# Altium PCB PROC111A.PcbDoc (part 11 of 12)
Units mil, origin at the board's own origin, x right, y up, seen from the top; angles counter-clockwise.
Board outline 7700 x 2300 mil, 6 copper layers (Top Layer, GND 1, SIG 1, SIG 2, GND 2, Bottom Layer), stack 61.062 mil thick; 841 components, 632 nets, 2914 pads, 1627 vias.
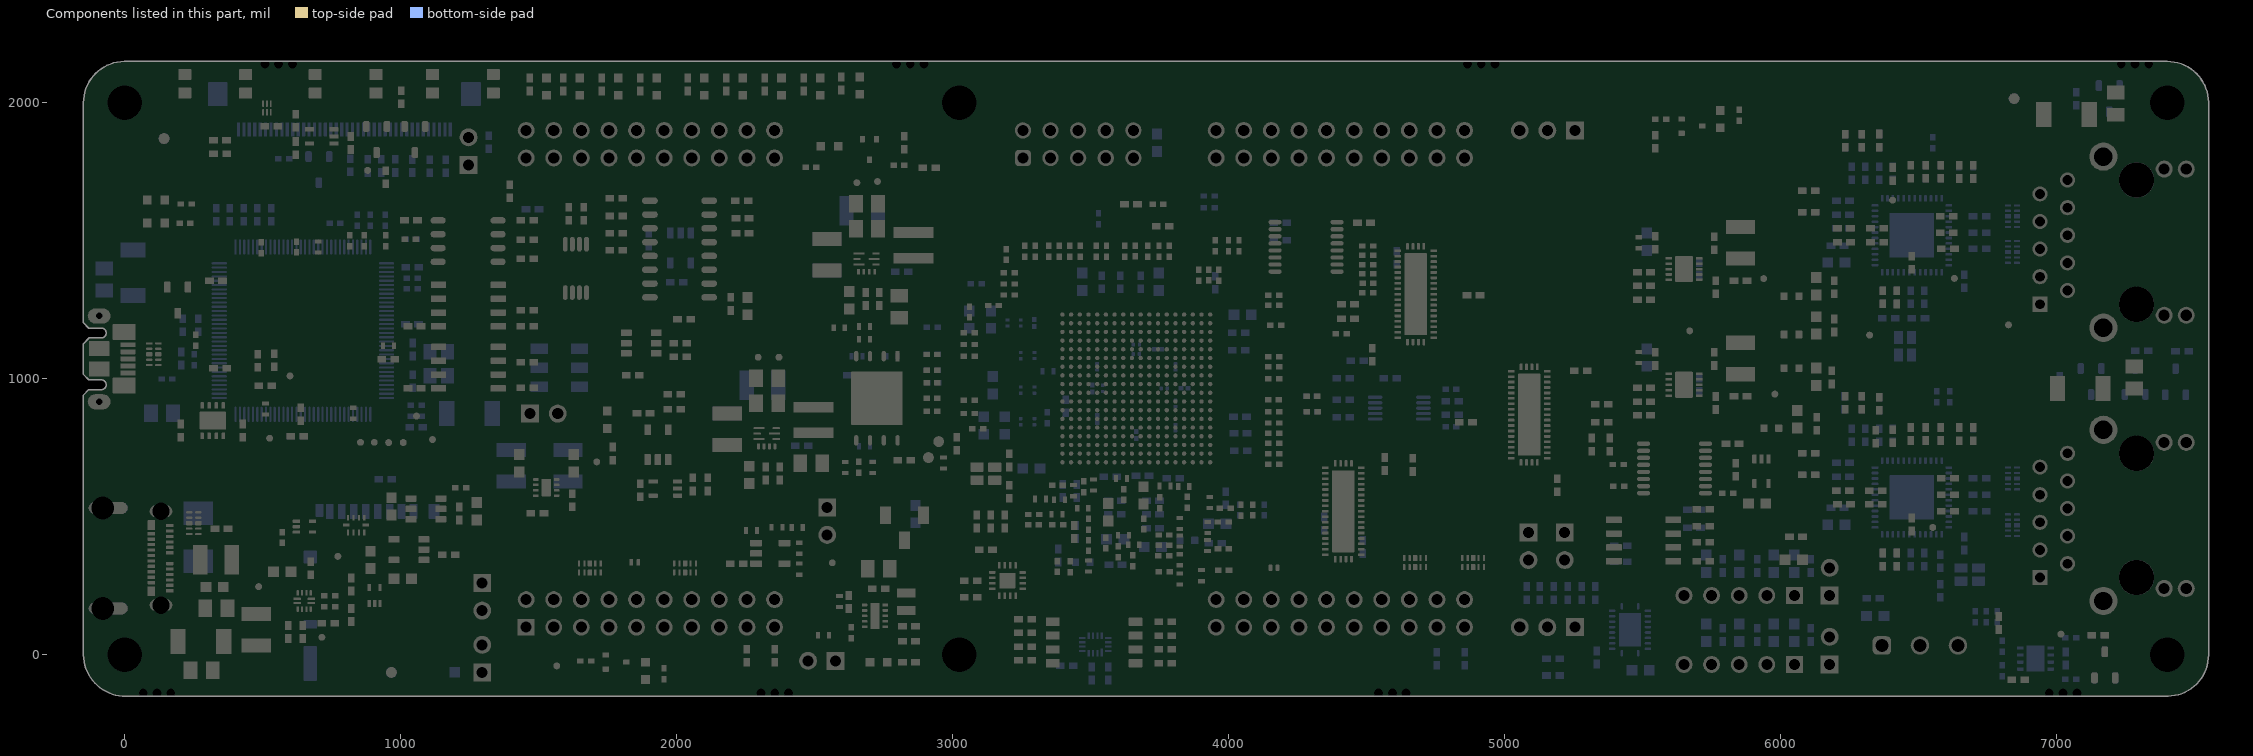
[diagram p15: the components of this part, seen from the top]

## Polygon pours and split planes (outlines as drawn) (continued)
VSYS_5V0_BP_2 on Bottom Layer "NONET_L-01_P-001" (solid, remove dead copper, pour order 310): 3796.91,-55.37 3814.39,-72.85 3902.52,-73.21 3997.16,-73.21 3997.16,230.51 3919.94,230.51 3861.66,172.24 3802.69,172.24 3745.77,115.32 3745.77,-3.83 3796.75,-54.81
VDDA_AM263_3V3 on Bottom Layer "Bottom Layer-VDDA_AM263_3V3" (solid, pour order 140): 18 vertices, not listed, extent 3543.61,365 3915,906.95
SHIELD4 on Bottom Layer "Bottom Layer-SHIELD4" (solid, remove dead copper, pour order 291): -135,818.11 20,818.11 20,1079.72 89.27,1148.99 89.27,1344.48 -135,1344.48
VBUS_XDS_5V0 on Bottom Layer "Bottom Layer-VBUS_USBMICRO_5V0" (solid, pour order 292): 125,1020 134,1020 144.96,1009.04 144.96,926.25 125,906.28 125,813.15 45,813.15 45,1020
GND on Bottom Layer "Bottom Layer-GND 4" (solid, pour order 56): 2446.67,1720 2446.67,1482.62 2641.67,1482.62 2641.67,1720
GND on Bottom Layer "Bottom Layer-GND 10" (solid, pour order 251): 3037.54,1305 3017.54,1285 3017.54,1242.46 3035,1225 3169.11,1225 3188.23,1205.88 3381.63,1205.88 3403.51,1227.76 3403.51,1269.82 3368.33,1305
GND on Bottom Layer "Bottom Layer-GND 12" (solid, pour order 247): 3237.13,839.09 3218.89,820.85 3066.76,820.85 3043.45,797.54 3043.45,724.17 3098.25,669.37 3208.92,669.37 3225.74,652.54 3267.54,652.54 3277.57,662.57 3277.57,738.68 3318.86,779.96 3318.86,830.8 3310.57,839.09
VDDS_AM263_LDO_1V8 on Bottom Layer "Bottom Layer-VDDS_AM263_LDO_1V8" (solid, pour order 289): 31 vertices, not listed, extent 3296.81,601.21 3919.75,1343.61
GND on Bottom Layer "Bottom Layer-GND 7" (solid, pour order 146): 3715,572.41 3715,314.12 3595,314.12 3595,572.41
SHIELD1 on Bottom Layer "NONET_L-01_P-001" (solid, remove dead copper, pour order 283): 26 vertices, not listed, extent -144.23,-103.9 263,582.61
VBUS_TYPEC_5V0 on Bottom Layer "NONET_L-01_P-001" (solid, remove dead copper, pour order 266): 20 vertices, not listed, extent 111.24,142.11 356.09,420
VDDA_AM263_1V8_LDO on Bottom Layer "Bottom Layer-VDDA_AM263_1V8_LDO" (solid, pour order 144): 3578.62,570 3578.62,310 3485,310 3485,376 3510,401 3510,570
GND on Bottom Layer "Bottom Layer-GND 2" (solid, pour order 80): 5415,1509.19 5605,1509.19 5605,1649.19 5415,1649.19
GND on Bottom Layer "Bottom Layer-GND 11" (solid, pour order 229): 26 vertices, not listed, extent 3494.11,920.33 3837.86,1070.93
GND on Bottom Layer "Bottom Layer-GND 1" (solid, pour order 94): 3080,985 3172.46,985 3188.58,968.21 3332.32,968.21 3332.32,1075 3080,1075
VDD_AM263_1V2 on Bottom Layer "Bottom Layer-VDD_AM263_1V2" (solid, pour order 92): 3157.05,965 3173.86,948.19 3315.57,948.19 3315.57,850.24 3225.88,850.24 3215.88,840 3080,840 3080,965
VDD_AM263_1V2 on Bottom Layer "Bottom Layer-VDD_AM263_1V2 1" (solid, pour order 90): 3034.87,1200 3034.87,1090 3315,1090 3315,1200
SHIELD2 on Bottom Layer "Top Layer-SHIELD2" (solid, pour order 192): 7100,179.68 7156.81,122.87 7262.87,122.87 7355,215 7355,266.54 7378.25,289.79 7500,289.79 7500,703.43 7385,703.43 7320,768.43 7320,990 7100,990
SHIELD3 on Bottom Layer "Top Layer-SHIELD3" (solid, pour order 190): 7083.03,1980 7060,1956.97 7060,1813.31 7100,1773.31 7100,1127.87 7115,1112.87 7277.87,1112.87 7355,1190 7355,1256.54 7378.25,1279.79 7500,1279.79 7500,1693.43 7385,1693.43 7320,1758.43 7320,1980
GND on Bottom Layer "Bottom Layer-GND 9" (solid, pour order 180): 6395,1318.62 6395,1246.17 6323.24,1246.17 6323.24,1040.62 6560,1040.62 6560,1286.02 6500,1286.02 6500,1358.25 6395,1358.25 6395,1321.48
VSYS_5V0 on Bottom Layer "Bottom Layer-VSYS_5V0 1" (solid, pour order 82): 5340,1484.19 5340,1358.91 5545,1358.91 5545,1484.19
VDD_AM263_1V2 on Bottom Layer "Bottom Layer-VDD_AM263_1V2 3" (solid, pour order 44): 2340,1100 2340,905 2576.3,905 2576.3,1100
VSYS_3V3 on Bottom Layer "Bottom Layer-VSYS_3V3" (solid, pour order 58): 2701.67,1715 2701.67,1522.62 2966.67,1522.62 2966.67,1715
VSYS_3V3 on Bottom Layer "Bottom Layer-VSYS_3V3 1" (solid, pour order 142): 3950,530 3950,380.76 3865,380.76 3865,530
VSYS_TA_3V3 on Bottom Layer "Bottom Layer-VSYS_TA_3V3" (solid, pour order 134): 380,1935 380,1800 459.37,1800 459.37,1935
GND on Bottom Layer "Bottom Layer-GND 3" (solid, pour order 72): 5415,1090 5605,1090 5605,1230 5415,1230
VSYS_5V0 on Bottom Layer "Bottom Layer-VSYS_5V0 2" (solid, pour order 70): 5335,1065 5335,939.72 5545,939.72 5545,1065
VSYS_5V0 on Bottom Layer "Bottom Layer-VSYS_5V0 3" (solid, pour order 60): 2360,1437.62 2360,1287.62 2616.67,1287.62 2616.67,1422.62 2491.67,1422.62 2476.67,1437.62
GND on Bottom Layer "Bottom Layer-GND 5" (solid, pour order 46): 2085,1096.57 2085,850 2280,850 2280,1096.57
VSYS_5V0 on Bottom Layer "Bottom Layer-VSYS_5V0 4" (solid, pour order 42): 1999.88,805 1999.88,655 2255,655 2255,790 2130,790 2115,805
GND on Bottom Layer "Bottom Layer-GND" (solid, pour order 32): 1310,810 1310,715 1705,715 1705,810
VSYS_5V0 on Bottom Layer "Bottom Layer-VSYS_5V0" (solid, pour order 30): 1550,655 1550,565 1550,501.28 1795.21,501.28 1795.21,690 1675,690 1675,655
VSYS_3V3_BP on SIG 2 "NONET_L-01_P-001" (solid, remove dead copper, pour order 309): 25 vertices, not listed, extent 1241.21,-138.5 3987.3,214.8
VSYS_5V0 on SIG 2 "SIG 1-VSYS_5V0" (solid, remove dead copper, pour order 170): 50 vertices, not listed, extent 1225,-150.47 7080,1510
VSYS_3V3 on SIG 2 "SIG 2-VSYS_3V3" (solid, remove dead copper, pour order 196): 119 vertices, not listed, extent 50.56,-139.06 7515,2090
VDD_XDS3V3 on SIG 2 "SIG 1-VDD_XDS3V3" (solid, remove dead copper, pour order 299): 10,690 10,1680 545,1680 545,1595 1205,1595 1205,755 265,755 265,690
VDD_AM263_1V2 on SIG 2 "SIG 1-VDD_AM263_1V2" (solid, remove dead copper, pour order 168): 28 vertices, not listed, extent 2340,580.04 3900,1184.96
VSD_3V3 on SIG 2 "SIG 2-VSD_3V3" (solid, pour order 284): 859.78,660.43 981.74,660.43 981.74,418.27 569.78,418.27 569.78,601.65 859.78,601.65
SHIELD1 on SIG 2 "NONET_L-01_P-001" (solid, remove dead copper, pour order 279): 26 vertices, not listed, extent -144.23,-103.9 263,582.61
VDD_ETH2_1V1_FILT on SIG 2 "SIG 2-VDD_ETH2_1V1_FILT" (solid, pour order 12): 18 vertices, not listed, extent 6109.18,1283.78 6696.59,1784.26
VDD_ETH1_1V1_FILT on SIG 2 "SIG 2-VDD_ETH1_1V1_FILT" (solid, pour order 84): 17 vertices, not listed, extent 6188.15,539.1 6805,1189.91
SHIELD2 on SIG 2 "Top Layer-SHIELD2" (solid, pour order 211): 7100,179.68 7156.81,122.87 7262.87,122.87 7355,215 7355,266.54 7378.25,289.79 7500,289.79 7500,703.43 7385,703.43 7320,768.43 7320,990 7100,990
SHIELD3 on SIG 2 "Top Layer-SHIELD3" (solid, pour order 209): 7083.03,1980 7060,1956.97 7060,1813.31 7100,1773.31 7100,1127.87 7115,1112.87 7277.87,1112.87 7355,1190 7355,1256.54 7378.25,1279.79 7500,1279.79 7500,1693.43 7385,1693.43 7320,1758.43 7320,1980
VDDS_AM263_LDO_1V8 on SIG 2 "SIG 2-VDDS_AM263_LDO_1V8" (solid, pour order 14): 3994.81,1127.63 3926.04,1127.63 3911.86,1141.81 3843.63,1141.81 3843.63,1103.31 3907.7,1103.31 3941.01,1070 3990.09,1070 4004.85,1084.76 4004.85,1117.72 3993.94,1128.63
VDDS_AM263_LDO_1V8 on SIG 2 "SIG 2-VDDS_AM263_LDO_1V8 1" (solid, pour order 16): 3560,1155.1 3560,1266.01 3563.99,1270 3563.99,1310.97 3555,1319.95 3522.32,1319.95 3507.37,1305 3507.37,1265.8 3480.74,1239.17 3480.74,1165.74 3501.48,1145 3549.9,1145
GND on GND 1 "GND 1-GND" (solid, remove dead copper, pour order 200): 55 vertices, not listed, extent -150,-150 7520,2150.53
SHIELD4 on GND 1 "Bottom Layer-SHIELD4" (solid, pour order 298): 27 vertices, not listed, extent -135,818.11 89.84,1344.61
GND_XDS on GND 1 "SIG 1-VDD_XDS3V3" (solid, pour order 150): 30,1132.67 96.18,1132.67 96.18,1372.54 30,1372.55 -109.74,1372.55 -109.74,1680 545,1680 545,1595 1205,1595 1205,765 265,765 30,765 30,1009.28 30,1035.32
SHIELD1 on GND 1 "NONET_L-01_P-001" (solid, remove dead copper, pour order 275): 26 vertices, not listed, extent -144.23,-103.9 263,582.61
SHIELD3 on GND 1 "Top Layer-SHIELD3" (solid, pour order 235): 7083.03,1980 7060,1956.97 7060,1813.31 7100,1773.31 7100,1127.87 7115,1112.87 7277.87,1112.87 7355,1190 7355,1256.54 7378.25,1279.79 7500,1279.79 7500,1693.43 7385,1693.43 7320,1758.43 7320,1980
SHIELD2 on GND 1 "Top Layer-SHIELD2" (solid, pour order 203): 7100,179.68 7156.81,122.87 7262.87,122.87 7355,215 7355,266.54 7378.25,289.79 7500,289.79 7500,703.43 7385,703.43 7320,768.43 7320,990 7100,990
GND on SIG 1 "NONET_L-01_P-001" (solid, remove dead copper, pour order 316): -15.19,2149.23 7451.59,2149.23 7550,2050.82 7550,-68.99 7468.99,-150 -18.42,-150 -148.4,-20.02 -148.4,2018.56 -18.05,2148.91
VUSB_5V0 on SIG 1 "NONET_L-01_P-001" (solid, remove dead copper, pour order 315): 25 vertices, not listed, extent 2481.98,-150 5432.82,501.78
VSYS_3V3 on SIG 1 "NONET_L-01_P-001" (solid, remove dead copper, pour order 307): 1235.65,-20.36 1239.07,-16.94 1240.24,-16.94 1330.39,-16.94 1344.91,-31.47 2205,-31.47 2411.62,-31.47 2430.37,-50.22 2430.37,-118.32 2411.86,-136.83 1254.42,-136.83 1231.17,-113.58 1231.17,-25.9
VSYS_5V0_BP_1 on SIG 1 "NONET_L-01_P-001" (solid, remove dead copper, pour order 313): 1236.81,202.96 1222.18,188.33 1222.18,95.77 1236.96,80.99 1347.29,80.99 1410.47,144.17 1479.37,144.17 1498.79,163.59 1498.79,229.57 1481.55,246.81 1372.11,246.81 1328.26,202.96
VDDA18_AM263_OSC_PLL on SIG 1 "SIG 1-VDDA18_AM263_OSC_PLL" (solid, remove dead copper, pour order 261): 21 vertices, not listed, extent 3320,426.7 3498.81,784.4
VDDA_AM263_1V8_LDO on SIG 1 "SIG 1-VDDA_AM263_1V8_LDO" (solid, pour order 217): 24 vertices, not listed, extent 3482.52,491.74 3992.51,899.87
SHIELD1 on SIG 1 "NONET_L-01_P-001" (solid, remove dead copper, pour order 277): 20 vertices, not listed, extent -144.23,-103.9 224.84,582.61
VDDS_AM263_LDO_1V8 on SIG 1 "SIG 1-VDDS_AM263_LDO_1V8 3" (solid, pour order 219): 3837.37,1098.64 3845,1091.01 3989.08,1091.01 3995.95,1097.88 3995.95,1114.05 3985,1125 3939.77,1125 3931.83,1117.05 3882.51,1117.05 3860.16,1139.4 3841.97,1139.4 3837.37,1134.8
VDDS_AM263_LDO_1V8 on SIG 1 "SIG 1-VDDS_AM263_LDO_1V8" (solid, pour order 221): 3423.07,758.07 3347,682 3347,630.82 3357.82,620 3426.79,620 3445,638.21 3445,720.25 3459.75,735 3459.75,748.64 3450.33,758.07
VDDS_AM263_LDO_1V8 on SIG 1 "SIG 1-VDDS_AM263_LDO_1V8 1" (solid, pour order 227): 3524.62,1310 3514.99,1300.37 3514.99,1159.77 3531.25,1143.51 3559.82,1143.51 3575,1158.69 3575,1300 3565,1310
SHIELD2 on SIG 1 "Top Layer-SHIELD2" (solid, pour order 207): 7100,179.68 7156.81,122.87 7262.87,122.87 7355,215 7355,266.54 7378.25,289.79 7500,289.79 7500,703.43 7385,703.43 7320,768.43 7320,990 7100,990
SHIELD3 on SIG 1 "Top Layer-SHIELD3" (solid, pour order 205): 7083.03,1980 7060,1956.97 7060,1813.31 7100,1773.31 7100,1127.87 7115,1112.87 7277.87,1112.87 7355,1190 7355,1256.54 7378.25,1279.79 7500,1279.79 7500,1693.43 7385,1693.43 7320,1758.43 7320,1980
VSYS_3V3 on SIG 1 "SIG 1-VSYS_3V3" (solid, remove dead copper, pour order 172): 3611.09,1165 3590.37,1165 3584.14,1158.77 3584.14,1130.46 3484.97,1130.46 3485.03,1048.85 3480.01,1043.83 3464.32,1043.83 3463.09,1042.6 3463.09,1026.15 3482.58,1006.66 3654.17,1006.66 3654.17,1137.1 3625.08,1166.2 3611.09,1166.2
GND on GND 2 "GND 1-GND" (solid, remove dead copper, pour order 280): 55 vertices, not listed, extent -150,-150 7520,2150.53
SHIELD4 on GND 2 "Bottom Layer-SHIELD4" (solid, pour order 305): 20,1122.51 89.84,1192.35 89.84,1227.7 89.84,1344.61 -135,1344.61 -135,818.11 20,818.11
GND_XDS on GND 2 "SIG 1-VDD_XDS3V3" (solid, pour order 303): 30,1132.67 96.18,1132.67 96.18,1372.54 30,1372.55 -109.74,1372.55 -109.74,1680 545,1680 545,1595 1205,1595 1205,765 265,765 30,765 30,1009.28 30,1035.32
SHIELD1 on GND 2 "NONET_L-01_P-001" (solid, remove dead copper, pour order 281): 26 vertices, not listed, extent -144.23,-103.9 263,582.61
SHIELD2 on GND 2 "Top Layer-SHIELD2" (solid, pour order 239): 7100,179.68 7156.81,122.87 7262.87,122.87 7355,215 7355,266.54 7378.25,289.79 7500,289.79 7500,703.43 7385,703.43 7320,768.43 7320,990 7100,990
SHIELD3 on GND 2 "Top Layer-SHIELD3" (solid, pour order 215): 7083.03,1980 7060,1956.97 7060,1813.31 7100,1773.31 7100,1127.87 7115,1112.87 7277.87,1112.87 7355,1190 7355,1256.54 7378.25,1279.79 7500,1279.79 7500,1693.43 7385,1693.43 7320,1758.43 7320,1980

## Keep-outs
Keep-Out Layer:
  lines w60: -150,650.57 310,650.57 310,715 1250,715 1250,1650 600,1650 600,1725 -150,1720.81
  text ".Layer_Name" at 427,-1008.49 h60

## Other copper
Top Layer:
  rectangle net VPP_AM263_1V7: 2409.44,392.94 2456.32,439.92
  rectangle net VPP_AM263_1V7: 2368.73,392.9 2444.39,433.12
  rectangle net VPP_AM263_1V7: 2368.13,392.9 2439.93,473.96
  rectangle net VSYS_5V0: 2266.63,389.49 2323.02,462.13
  text ".Layer_Name" at 427,-1008.49 h60
SIG 1:
  text ".Layer_Name" at 427,-1008.49 h60
SIG 2:
  text ".Layer_Name" at 427,-1008.49 h60
GND 1:
  text ".Layer_Name" at 427,-1008.49 h60
GND 2:
  pour cut-out: 6465.23,-33.23 6509.62,-77.62 6700.55,-77.62 6726.24,-51.93 6813.07,-51.93 6830,-35 6852.47,-35 6856.02,-38.54 6879.53,-38.54 6884.85,-33.23 6884.85,5.15 6880,10 6834.84,10 6820,24.84 6774.96,24.84 6756.1,5.98 6705.75,5.98 6690,21.73 6690,55 6665,80 6601.56,80 6585,63.44 6585,22.77 6562.23,0 6435,0 6415,20 6415,60 6395,80 6333.81,80 6323.24,69.43 6323.24,55 6323.32,-13.55 6343,-33.23
  text ".Layer_Name" at 427,-1008.49 h60
Bottom Layer:
  rectangle net SHIELD4: -123.86,1224.13 88.72,1343.6
  rectangle net GND_XDS: -110,1372.17 87.08,1511.11
  text ".Layer_Name" at 427,-1008.49 h60

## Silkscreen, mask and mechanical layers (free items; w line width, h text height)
Top Overlay:
  drawing of 71 lines, arcs and shapes, not listed
  text "SW4" at 981.5,2096.76 h25
  text "SW3" at 550,2080 h25
  text "ASSY" at 4015,2005 h108.27
  text "GND" at 1425.74,2003.31 h40 r90
  text "GND" at 3979,2000 h40 r90
  text "FSI" at 3330,1996.38 h100
  text "SL#" at 5945,1990 h108.27
  text "3V3" at 5305.61,1970 h25 r90
  text "GND" at 5165,1962.06 h25 r90
  text "GND" at 5067.15,1960 h25 r90
  text "RESETn" at 685,1950 h50
  text "INT1" at 1269.88,1950 h25
  text "D4" at 2633.82,1950 h25
  text "D7" at 2492.5,1949 h25
  text "D14" at 1510,1945 h25
  text "D13" at 1620,1945 h25
  text "D12" at 1760.31,1945 h25
  text "D11" at 1900.31,1945 h25
  text "D10" at 2071.73,1945 h25
  text "D9" at 2220,1945 h25
  text "D8" at 2360,1945 h25
  text "SW2" at 140,1937.06 h25
  text "PORZ" at 280.11,1918.5 h50
  text "Q10" at 2678,1903.57 h25
  text "DS1" at 2491.81,1882.06 h25
  text "J12" at 5095.35,1794.87 h25
  text "U33" at 677.55,1777.02 h25
  text "J8" at 6783.56,1760 h25
  text "ERROR" at 2534,1755.5 h30
  text "J1" at 1136,1739.5 h25
  text "J23" at 3425.61,1706.28 h25
  text "U48" at 1978.41,1692.03 h25
  text "U23" at 4632,1502.52 h25
  text "U31" at 5611.91,1491.88 h25
  text "D3" at 77.44,1490.13 h25
  text "U25" at 1016.36,1425.43 h25
  text "LP-AM263" at 4978.09,1405.53 h75
  text "U35" at 1721.68,1340.54 h25
  text "XDS110" at -114.82,1322.48 h50
  text "U26" at 995,1293.54 h25
  text "'.PRJ_Number''.PCB_Rev'" at 4978.09,1285.72 h75
  text "UART0" at -110.42,1284.4 h50
  text "U1" at 3358.09,1284.14 h25
  text "U28" at 273.39,1266 h25
  text "ICSSM_MII0" at 6833.84,1245.24 h60 r90
  text "CPSW RGMII2/" at 6768.84,1241.97 h60 r90
  text "J34" at 65.78,1168 h25
  text "U2" at 1714.39,1115 h25
  text "U30" at 5616.51,1092.07 h25
  text "U7" at 2541.67,1046.41 h25
  text "U27" at 1001.79,1003.83 h25
  text "Caution" at 3133.18,964.53 h30
  text "L2" at 2536.09,951.68 h25
  text "U45" at 320.31,939.61 h25
  text "J17" at 1601.08,940 h25 r90
  text "D2" at 1733.5,934.15 h25
  text "U44" at 78.02,924.16 h25
  text "Hot" at 3186.02,912.04 h30
  text "Surface" at 3136.56,871.97 h30
  text "ADC_VREF" at 1675,825 h30 r90
  text "TP26" at 1125.5,798.54 h25 r90
  text "U49" at 5586.51,797.43 h25
  text "U29" at 2270,771.24 h25 r90
  text "U5" at 2009.45,745.04 h25
  text "J7" at 6788.53,710 h25
  text "U19" at 1492.67,678.66 h25
  text "Y1" at 2991.94,627.58 h25
  text "PWR IN" at -100.95,597.47 h80
  text "J5" at 181.7,573.39 h25
  text "J18" at 2405.92,553.9 h25
  text "3V3" at 5055,525 h25
  text "5V0" at 5197.64,513.97 h25
  text "U6" at 1937.02,512 h25
  text "J16" at 6144.58,389.14 h25
  text "5V" at 1439.29,336.16 h40 r90
  text "DAC_VREF" at 2830.44,334.18 h50
  text "GND" at 1542.15,315.02 h40 r90
  text "EQEP2" at 5813.56,280.94 h50
  text "U15" at 4846.51,261.21 h25
  text "U14" at 4626.51,254.83 h25
  text "U12" at 1585,247.64 h25
  text "J13" at 5041.02,244.66 h25
  text "J14" at 5176.51,239.83 h25
  text "ICSSM_MII1" at 6850,213.27 h60 r90
  text "CPSW RGMII1/" at 6785,210 h60 r90
  text "J33" at 6380,203 h25
  text "SW1" at 3461.51,194.83 h25
  text "MCAN0" at 6535,194.96 h30
  text "J25" at 5495,180 h25
  text "J11" at 5099.61,175.69 h25
  text "J10" at 1229.53,162.59 h25 r90
  text "U3" at 3164.74,154.61 h25
  text "EQEP0" at 5780,60 h50
  text "J15" at 6026.51,50.93 h25
  text "U36" at 2685.07,29.96 h25
  text "D5" at 1865,27.19 h25
  text "J24" at 5496.51,-35.17 h25
  text "5V0" at 5278.52,-40 h25 r90
  text "CANA_N" at 6280,-40 h30 r90
  text "J9" at 1225.17,-40.99 h25 r90
  text "GND" at 5072.77,-56.84 h25 r90
  text "GND" at 5174.39,-60 h25 r90
  text "Q5" at 7044.84,-69.1 h25
  text "HIGH" at 3214,-106.5 h30
  text "LOW" at 3735,-106.5 h30
  text "D6" at 2655,-108.15 h25
  text "CANA_P" at 6760,-110.1 h30 r90
  text "BOOTMODE" at 3393,-132.5 h30
  text ".Layer_Name" at 427,-1008.49 h60
Bottom Overlay:
  drawing of 4430 lines, arcs and shapes, not listed
  text "J6" at 278.69,1911.38 h25
  text "Q7" at 7186.65,1893.21 h25
  text "Q1" at 720,1835.02 h25
  text "TEST AUTOMATION HEADER" at 526.94,1780 h30
  text "U40" at 6860,1673.21 h25
  text "www.ti.com/launchpad" at 5378.5,1645.7 h30
  text "U37" at 6285.43,1489.18 h25 r270
  text "U9" at 2165,1454.88 h25
  text "U24" at 294.7,1402.53 h25
  text "U41" at 6858.56,1350.78 h25
  text "VREF Select" at 1725.39,1185.55 h30
  text "Y3" at 1182.98,1160 h25
  text "LP-AM263" at 5179,1155.7 h30
  text "4" at 1446.57,1097.62 h25
  text "1" at 1714.39,1095 h25
  text "Development Kit" at 5281,1075.7 h30
  text "6" at 1452.07,954.9 h25
  text "3" at 1725.39,954.9 h25
  text "Q4" at 7115,877.71 h25
  text "Q8" at 7317.49,871.98 h25
  text "Q9" at 7445,861.5 h25
  text "U17" at 4650,778.21 h25
  text "U38" at 6867.5,721.84 h25
  text "J2" at 763.55,580.04 h25
  text "uSD" at 1244.83,561.39 h108.27
  text "U22" at 6310.13,385 h25
  text "U39" at 6860,360.96 h25
  text "5V" at 1431.69,290.69 h40 r270
  text "5V" at 3919.42,289.86 h40 r270
  text "GND" at 1532.26,289.03 h36 r270
  text "GND" at 4034.24,286.69 h36 r270
  text "Y2" at 6810,279.59 h25
  text "U43" at 5490,210 h25
  text "U42" at 6955,80 h25
  text "U4" at 3645,63.21 h25
  text "Q6" at 7270,46.5 h25
  text "3V3" at 1428.18,-90.67 h40 r270
  text "3V3" at 3932.73,-93.03 h40 r270
  text ".Layer_Name" at 427,-1008.49 h60
Top Paste:
  text ".Layer_Name" at 427,-1008.49 h60
Bottom Paste:
  text ".Layer_Name" at 427,-1008.49 h60
Top Solder:
  text ".Layer_Name" at 427,-1008.49 h60
  text ".Layer_Name" at 427,-1008.49 h60
Bottom Solder:
  text ".Layer_Name" at 427,-1008.49 h60
Drill Guide:
  text ".Layer_Name" at 427,-1008.49 h60
M1 Board Outline:
  lines w6: -18.84,-226.94 41.79,-226.94 ccw(c41.79,-187.57) 81.16,-187.57 ccw(c41.79,-187.57) 41.79,-148.2 ; 191.4,-226.94 cw(c191.4,-187.57) 152.03,-187.57 cw(c191.4,-187.57) 191.4,-148.2 ; 5729.19,2229 5789.82,2229 ; 7208.59,2150.26 ccw(c7208.59,2189.63) 7247.96,2189.63 ccw(c7208.59,2189.63) 7208.59,2229 ; 7208.59,4809.26 ccw(c7208.59,4848.63) 7247.96,4848.63 ccw(c7208.59,4848.63) 7208.59,4888 ; 7358.2,2150.26 cw(c7358.19,2189.63) 7318.83,2189.63 cw(c7358.19,2189.63) 7358.2,2229 7418.83,2229 ; 7358.2,4809.26 cw(c7358.19,4848.63) 7318.83,4848.63 cw(c7358.19,4848.63) 7358.2,4888 7418.83,4888 ; -154.17,2230 7545.83,2230 7545.83,2430 -154.17,2430 -154.17,2230 ; -154.17,4889 -154.17,5089 7545.83,5089 7545.83,4889 -154.17,4889 ; -145.84,-427.94 -145.84,-227.94 7554.16,-227.94 7554.16,-427.94 -145.84,-427.94
  lines w10: -150,1017.07 -150,1016.08 ; -150,3676.07 -150,3675.08 ; -2.06,2149.99 ccw(c0,2000) -150,1999.99 -150,1278.88 ; -2.06,4808.99 ccw(c0,4659) -150,4658.99 -150,3937.88 ; 0,-150 7400,-149.99 ; 0,2150 7400,2150 cw(c7400,2000) 7549.99,2002.06 ; 0,2509 7400,2509.01 ; 0,4809 7400,4809 cw(c7400,4659) 7549.99,4661.06 ; 4.17,-150 cw(c2.09,2.09) -150,0 -150,941.28 cw(c-130.32,941.28) -130.32,960.97 -84.25,960.97 ccw(c-84.25,977.87) -67.34,977.87 ccw(c-85.87,977.87) -85.87,996.4 -130.32,996.4 cw(c-130.32,1016.08) -150,1016.08 ; 4.17,2509 cw(c2.09,2661.09) -150,2659 -150,3600.28 cw(c-130.32,3600.28) -130.32,3619.97 -84.25,3619.97 ccw(c-84.25,3636.87) -67.34,3636.87 ccw(c-85.87,3636.87) -85.87,3655.4 -130.32,3655.4 cw(c-130.32,3675.08) -150,3675.08 ; 7402.06,-149.99 ccw(c7400,0) 7550,0.01 7550,2000 ; 7402.06,2509.01 ccw(c7400,2659) 7550,2659.01 7550,4659 ; -150,1016.08 -150,1128.29 cw(c-130.32,1128.29) -130.32,1147.97 -85.04,1147.97 ccw(c-85.04,1165.67) -67.34,1165.67 -67.34,1166.5 ccw(c-84.25,1166.5) -84.25,1183.41 -85.04,1183.41 ; -150,1278.88 -150,1203.09 ccw(c-130.32,1203.09) -130.32,1183.41 ; -150,1278.88 -150,1278.88 ; -150,3675.08 -150,3787.29 cw(c-130.32,3787.29) -130.32,3806.97 -85.04,3806.97 ccw(c-85.04,3824.67) -67.34,3824.67 -67.34,3825.5 ccw(c-84.25,3825.5) -84.25,3842.41 -85.04,3842.41 ; -150,3937.88 -150,3937.88 ; -150,3937.88 -150,3862.09 ccw(c-130.32,3862.09) -130.32,3842.41 -85.04,3842.41 ; -130.32,1183.41 -85.04,1183.41 ; -130.32,1183.41 -85.04,1183.41 ; -85.04,1183.41 ccw(c-85.04,1183.41) -85.04,1183.41 ; -85.04,3842.41 ccw(c-85.04,3842.41) -85.04,3842.41
  text ".Layer_Name" at 427,-930 h40
M2 Board Dimensions:
  rectangle: 10072.36,-371.24 10197.36,-246.24
  rectangle: 10197.36,-496.24 10572.36,-371.24
  lines w7: 10072.36,-371.24 11072.36,-371.24 ; 10197.36,-496.24 10197.36,-246.24 ; 10322.36,-496.24 10322.36,-246.24 ; 10572.36,-496.24 10572.36,-246.24 ; 10822.36,-496.24 10822.36,-246.24 ; 10072.36,-496.24 11072.36,-496.24 11072.36,-246.24 10072.36,-246.24 10072.36,-496.24
  text ".Layer_Name" at 427,-1008.49 h60
M3 3D STEP Top:
  text ".Layer_Name" at 427,-1008.49 h60
M4 3D STEP Bottom:
  text ".Layer_Name" at 427,-1008.49 h60
Assembly Top/Assembly Bottom Top:
  circle w5: c598.48,1010.35 r22.88
  circle w5: c2563.35,333.41 r22.88
  circle w5: c524.75,784.53 r22.88
  circle w5: c1008.9,769 r22.88
  circle w5: c955.9,769 r22.88
  circle w5: c903.9,770 r22.88
  circle w5: c853.9,770 r22.88
  circle w5: c1115,779.89 r22.88
  circle w5: c1057.03,865 r22.88
  circle w5: c7015,75 r22.88
  circle w5: c880,1755 r22.88
  circle w5: c1710,698.96 r22.88
  circle w5: c485.03,247.07 r22.88
  circle w5: c5978.41,944.72 r22.88
  circle w5: c2370,1078.07 r22.88
  circle w5: c2295,1078.07 r22.88
  circle w5: c2652.41,1710.51 r22.88
  circle w5: c2727.25,1715 r22.88
  circle w5: c5938.14,1363.04 r22.88
  lines w10: -442,-1080.17 6158,-1080.17 ; -442,-876.83 6160,-876.83 ; -442,-673.5 -442,-1283.5 3563,-1283.5 6160,-1283.5 6160,-673.5 -441.5,-673.5 -441.5,-1283.5 1134,-1283.5 ; 2023,-1283.5 2023,-673.5 ; 3290,-876.83 3290,-673.5 ; 4130,-876.83 4130,-673.5 ; 4752,-1290 4752,-1087.17
  text "TP9" at 2681.43,1744.68 h25
  text "TP18" at 756.66,1742.84 h25
  text "TP14" at 2581.88,1739.98 h25
  text "TP11" at 5928.64,1392.41 h25
  text "TP10" at 2357.16,1110.67 h25
  text "TP15" at 2239.35,1110.36 h25
  text "TP12" at 5942.64,975.57 h25
  text "TP24" at 657.92,964.56 h25 r90
  text "TP23" at 986.5,894.47 h25
  text "TP8" at 1668.52,728.62 h25
  text "TP25" at 469.79,726.97 h25
  text "TP26" at 1072.54,722.8 h25
  text "TP27" at 866.82,648.93 h25 r90
  text "TP28" at 915.9,647.04 h25 r90
  text "TP30" at 1023.1,644.78 h25 r90
  text "TP29" at 972.45,643.12 h25 r90
  text "TP4" at 435.27,274.42 h25
  text "TP6" at 2530.02,270.07 h25
  text "TP22" at 6944.47,104.47 h25
  text "COMPONENTS MARKED 'DNP' SHOULD NOT BE POPULATED." at 1008.92,-528.5 h60
  text "ASSEMBLY VARIANT:" at 1008.42,-644 h60
  text ".VariantName" at 2044.42,-644 h60
  text "PCB VIEWED FROM TOP SIDE" at -378.5,-805.67 h60
  text "BOARD #:" at 2098,-805.67 h60
  text ".PRJ_Number" at 2643.5,-805.67 h60
  text "REV:" at 3488,-805.67 h60
  text ".PCB_Rev" at 3779.5,-805.67 h60
  text "SVN REV:" at 4326,-805.67 h60
  text ".VersionControl_RevNumber" at 4832,-805.67 h60
  text "TID #:" at 2098,-1009 h60
  text ".TID" at 2643.5,-1009 h60
  text "PLOT NAME =" at -378.5,-1214.34 h60
  text ".plot_File_Name" at 427,-1214.34 h60
  text "GENERATED    :" at 2100,-1214.34 h60
  text ".Print_Date" at 2969.5,-1214.34 h60
  text ".Print_Time" at 3698.5,-1214.34 h60
  text "TEXAS INSTRUMENTS" at 4963,-1214.34 h60
Assembly Top/Assembly Bottom Bottom:
  lines w10: -442.5,-877.33 6159.5,-877.33 ; -440.5,-1080.67 6159.5,-1080.67 ; 965.5,-1290.5 965.5,-1087.67 ; 1587.5,-877.33 1587.5,-674 ; 2427.5,-877.33 2427.5,-674 ; 3694.5,-1284 3694.5,-674 ; 4583.5,-1284 6159,-1284 6159,-674 -442.5,-674 -442.5,-1284 2154.5,-1284 6159.5,-1284 6159.5,-674
  text "COMPONENTS MARKED 'DNP' SHOULD NOT BE POPULATED." at 5952,-528 h60
  text ".VariantName" at 4908,-644 h60
  text "ASSEMBLY VARIANT:" at 5947,-644 h60
  text ".VersionControl_RevNumber" at 885.5,-806.17 h60
  text "SVN REV:" at 1391.5,-806.17 h60
  text ".PCB_Rev" at 1938,-806.17 h60
  text "REV:" at 2229.5,-806.17 h60
  text ".PRJ_Number" at 3074,-806.17 h60
  text "BOARD #:" at 3619.5,-806.17 h60
  text "PCB VIEWED FROM BOTTOM SIDE" at 6096,-806.17 h60
  text ".TID" at 3074,-1009.5 h60
  text "TID #:" at 3619.5,-1009.5 h60
  text "TEXAS INSTRUMENTS" at 754.5,-1214.84 h60
  text ".Print_Time" at 2019,-1214.84 h60
  text ".Print_Date" at 2748,-1214.84 h60
  text "GENERATED    :" at 3617.5,-1214.84 h60
  text ".plot_File_Name" at 5290.5,-1214.84 h60
  text "PLOT NAME =" at 6096,-1214.84 h60
M9 Title Sheet:
  drawing of 57 lines, arcs and shapes, not listed
  text "1" at 589.84,7886.5 h70
  text "2" at 3085.5,7886.5 h70
  text "3" at 5574.84,7886.5 h70
  text "4" at 8044.51,7886.5 h70
  text "5" at 10543.5,7886.5 h70
  text "6" at 13085.5,7886.5 h70
  text "A" at -566.5,6743.5 h70
  text "A" at 14233.5,6743.5 h70
  text "B" at -566.5,4363.5 h70
  text "B" at 14233.5,4363.5 h70
  text "C" at -566.5,1988.5 h70
  text "C" at 14233.5,1988.5 h70
  text "PROJECT TITLE:" at 11193.5,127.5 h45
  text ".PRJ_Title" at 11243.5,-5.83 h70
  text "DESIGNED FOR:" at 11193.5,-173.5 h45
  text ".PRJ_Customer" at 11243.5,-313.5 h70
  text "D" at -566.5,-381.5 h70
  text "D" at 14233.5,-381.5 h70
  text "FILE NAME:" at 11193.5,-473.5 h45
  text ".PCB_File_Name_No_Path" at 11243.5,-593.5 h70
  text "Texas Instruments (TI) and/or its licensors do not warrant the accuracy or completeness of this specification" at 6224,-755.34 h45
  text "ENGINEER:" at 11193.5,-763.5 h45
  text "LAYOUT BY:" at 12698.5,-763.5 h45
  text "or any information contained therein. TI and/or its licensors do not warrant that this design will meet" at 6179.01,-868 h45
  text ".PRJ_Engineer" at 11243.5,-918.49 h70
  text ".PCB_Layout" at 12749,-918.49 h70
  text "the specifications, will be suitable for your application or fit for any particular purpose, or will operate in" at 6179.01,-980.67 h45
  text "ALTIUM DESIGNER VERSION:" at 12698.5,-1073.5 h45
  text "an implementation. TI and/or its licensors do not warrant that the design is production worthy. You should" at 6179.01,-1093.33 h45
  text "completely validate and test your design implementation to confirm the system functionality for your application." at 6224,-1206 h45
  text ".print_Scale" at 11243.5,-1206.83 h70
  text ".Application_BuildNumber" at 12749,-1206.83 h70
  text "1" at 589.84,-1413.5 h70
  text "2" at 3085.5,-1413.5 h70
  text "3" at 5574.84,-1413.5 h70
  text "4" at 8081.51,-1413.5 h70
  text "5" at 10580.5,-1413.5 h70
  text "6" at 13085.5,-1413.5 h70
M10 Fab Notes:
  drawing of 220 lines, arcs and shapes, not listed
  text "SL#" at 7720,7515.45 h100
  text "LAYER" at 10020,7500 h100
  text "WIDTH(Mils)" at 10500,7500 h100
  text "SPACE(Mils)" at 11280,7500 h100
  text "IMPEDANCE(Ohms)" at 12100,7500 h100
  text "REF LAYER" at 13380,7500 h100
  text "TYPE" at 9060,7480 h100
  text "50" at 12700,7274.09 h100
  text "L02,L05" at 13509.77,7274.09 h100
  text "L1,L6" at 10121.22,7270.32 h100
  text "01" at 7760,7265.45 h100
  text "MICROSTRIP" at 8027.59,7260 h100
  text "5.3" at 10860,7260 h100
  text "NA" at 11680,7260 h100
  text "L02,L05" at 13510.44,7104.6 h100
  text "02" at 7760.19,7103.78 h100
  text "EDGE COUPLED MICROSTRIP" at 8029.1,7099.74 h100
  text "4.2" at 10860,7100 h100
  text "5" at 11760,7100 h100
  text "90" at 12700,7100 h100
  text "L1,L6" at 10121.22,7095.32 h100
  text "03" at 7760.19,6928.78 h100
  text "EDGE COUPLED MICROSTRIP" at 8029.1,6925.36 h100
  text "L02,L05" at 13509.77,6924.09 h100
  text "L1,L6" at 10121.22,6920.32 h100
  text "7.7" at 11700,6920 h100
  text "100" at 12641,6920 h100
  text "4" at 10896.99,6916.45 h100
  text "04" at 7760.19,6753.78 h100
  text "EDGE COUPLED MICROSTRIP" at 8029.1,6750.36 h100
  text "L05" at 13509.77,6749.09 h100
  text "L6" at 10121.22,6745.32 h100
  text "4.1" at 10896.99,6741.45 h100
  text "6.8" at 11700,6740 h100
  text "120" at 12641,6740 h100
  text "STRIPLINE" at 8023.97,6582.99 h100
  text "05" at 7760.19,6578.78 h100
  text "L3" at 10125.27,6575.99 h100
  text "L02/04" at 13510.44,6575 h100
  text "4.75" at 10896.99,6566.45 h100
  text "NA" at 11720,6560 h100
  text "50" at 12720,6560 h100
  text "06" at 7760.19,6403.78 h100
  text "L3" at 10128.27,6399.99 h100
  text "6" at 11760,6400 h100
  text "EDGE COUPLED STRIPLINE" at 8037.65,6394.7 h100
  text "90" at 12723.7,6395 h100
  text "L02/04" at 13510.44,6395 h100
  text "4" at 10899.99,6390.45 h100
  text "DESIGN INFORMATION" at 12232.02,6206.17 h60
  text "IMPEDANCE SPECIFICATIONS" at 8775,6160 h100
  text "MIN. TRACK WIDTH:" at 11587.46,6074.05 h60
  text "4" at 12683.7,6074.05 h60
  text "MIL" at 12838.46,6074.05 h60
  text "MIN. CLEARANCE:" at 11587.46,5949.92 h60
  text "4" at 12683.7,5949.92 h60
  text "MIL" at 12838.46,5949.92 h60
  text "MIN. VIA PAD SIZE:" at 11587.46,5825.8 h60
  text "18" at 12653.71,5825.8 h60
  text "MIL" at 12838.46,5825.8 h60
  text "0.05mm (2MIL)" at 12282.46,5695.9 h60
  text "MINIMUM ANNULAR RING" at 11258.23,5687.67 h60
  text "EXTERNAL" at 12990.46,5687.67 h60
  text "PER" at 11458.23,5577.55 h60
  text "IPC-D-275 CLASS 2 LEVEL C" at 11678.23,5577.54 h60
  text "MIL, HOLES" at 13166.46,5477.07 h60
  text "+/-" at 12774,5468.48 h60
  text "+/-" at 13628,5468.48 h60
  text "REGISTRATION TOLERANCES:" at 11258.23,5467.42 h60
  text "METAL" at 12458,5467.42 h60
  text "5" at 13034.2,5467.42 h60
  text "3" at 13867.2,5467.42 h60
  text "MIL" at 13983.46,5467.42 h60
  text "HOLE SIZE TOLERANCE (UNLESS OTHERWISE SPECIFIED):" at 11258.23,5369.1 h60
  text "+/-" at 13628,5366.23 h60
  text "3" at 13867.2,5365.17 h60
  text "MIL" at 13983.46,5365.17 h60
  text "MATERIAL:" at 11183.46,5227.52 h60
  text "FR-4 High Tg" at 12169.9,5099 h60
  text "X" at 12025.46,5091.01 h60
  text "FR-408" at 11604.46,5086.49 h60
  text "OTHER" at 13092.46,5086.49 h60
  text "LAYER STACK UP TABLE" at 8355,5020 h100
  text "62 MIL (1.6mm) +/-10%" at 11924.56,4943.46 h60
  text "X" at 11804.46,4941.01 h60
  text "THICKNESS:" at 11258.23,4935.24 h60
  text "OTHER" at 13209.46,4935.24 h60
  text "TOLERANCE:" at 11258.23,4796.92 h60
  text "X" at 12106.46,4796.92 h60
  text "ANSI IPC-6012 TYPE 3 CLASS 2" at 12284.48,4796.92 h60
  text "OTHER +/-" at 12284.46,4652.73 h60
  text "BOW & TWIST:" at 11258.23,4507.54 h60
  text "X" at 12106.46,4507.54 h60
  text "ANSI IPC-6012 TYPE 3 CLASS 2" at 12284.48,4507.54 h60
  text "OTHER +/-" at 12284.46,4360.85 h60
  text "DRILLING:" at 11183.46,4230.23 h60
  text "NC_DRILL FILES" at 12944.46,4125.04 h60
  text "REFERENCE:" at 11258.23,4121.1 h60
  text "X" at 11915.46,4121.01 h60
  text "AS SHOWN" at 12093.46,4121.1 h60
  text "X" at 12816.46,4121.1 h60
  text "OTHER" at 13242.46,3978.85 h60
  text "PTH COPPER THICKNESS:" at 11257.91,3975.32 h60
  text "X" at 12397.14,3975.32 h60
  text "20-30 um" at 12525.14,3975.32 h60
  text "BOARD FINISH:" at 11183.46,3827.73 h60
  text "SILKSCREEN:" at 11338.68,3717.6 h60
  text "X" at 12296.46,3717.6 h60
  text "TOP" at 12413.46,3717.6 h60
  text "X" at 12806.46,3717.6 h60
  text "BOTTOM" at 12924.46,3717.6 h60
  text "SILKSCREEN COLOR:" at 11338.68,3562.41 h60
  text "X" at 12295.46,3562.41 h60
  text "WHITE" at 12413.46,3562.41 h60
  text "OTHER" at 12924.46,3562.41 h60
  text "GREEN" at 12544.46,3418.96 h60
  text "X" at 13018.46,3418.96 h60
  text "OTHER" at 13162.46,3418.96 h60
  text "RED" at 13521.46,3418.96 h60
  text "SOLDER RESIST COLOR:" at 11338.68,3412.1 h60
  text "X" at 12426.46,3264.71 h60
  text "MATTE" at 12544.46,3264.71 h60
  text "SEMI-GLOSS" at 13162,3264.07 h60
  text "IMMERSION GOLD (ENIG)" at 12244.46,3091.94 h60
  text "ENEPIG" at 13582,3084.72 h60
  text "SURFACE FINISH:" at 11183.46,3083.72 h60
  text "X" at 12066.46,3083.72 h60
  text "IMM. TIN/SILVER OR EQUIV" at 11513,2946.4 h60
  text "OTHER" at 12944.46,2942.47 h60
  text "ARRAY/PANEL:" at 11183.46,2787.09 h60
  text "X" at 12066.46,2787.09 h60
  text "CUT AND TRIM PER M1 BOARD OUTLINE" at 12244.46,2778.87 h60
  text "N.C. ROUTE" at 12244.46,2642.9 h60
  text "V. SCORE" at 13110.46,2642.9 h60
  text "CERTIFICATION:" at 11183.46,2513.77 h60
  text "MATERIALS AND WORKMANSHIP FOR ALL PCBS" at 11908.46,2513.77 h60
  text "TO MEET OR EXCEED THE REQUIREMENTS OF:" at 11908.46,2419.71 h60
  text "X" at 11545.97,2291.08 h60
  text "ANSI IPC-A-600F CLASS ->" at 11673.96,2291.08 h60
  text "X" at 13321.97,2291.08 h60
  text "2" at 13431.96,2291.08 h60
  text "1" at 13116.96,2289.58 h60
  text "3" at 13785.96,2289.58 h60
  text "X" at 12357.97,2143.39 h60
  text "RoHS" at 12485.96,2143.39 h60
  text "OTHER" at 13130.36,2143.39 h60
  text "PER ORDER" at 13527.42,2143.39 h60
  text "ALL BOARDS MUST MEET OR EXCEED UL94-V0 REQUIREMENTS." at 11211,1989.57 h60
  text "PCB MUST BEAR THE UL94V-0 UL REGISTERED MATERIAL ID NUMBER" at 11211,1873.5 h60
  text "ADDITIONAL REQUIREMENTS:" at 11183.46,1704.08 h60
  text "MICROSECTION:" at 11258.23,1596.95 h60
  text "YES" at 12163.96,1596.95 h60
  text "REQUIRED" at 13025.46,1452.62 h60
  text "BARE BOARD ELEC. TEST:" at 11258.23,1449.76 h60
  text "NONE" at 12563.96,1449.76 h60
  text "X" at 12907.46,1449.76 h60
  text "PER ORDER" at 13617.46,1449.76 h60
  text "XX MIL VIAS REQUIRE NON-CONDUCTIVE FILL AND PLANARIZE" at 11362.99,1273.56 h59
  text "XX MIL VIAS REQUIRE CONDUCTIVE FILL AND PLANARIZE" at 11370.99,1169.58 h60
  text "OUTER XX MIL TRACES REQUIRE 50 OHM SINGLE-ENDED IMPEDANCE" at 11370,1006.2 h58
  text "LAYER 2 & 3 (INNER LAYERS) XX MIL WIDE, XX MIL SPACE / TRACES REQUIRE 100 OHM DIFFERENTIAL IMPEDANCE" at 11362,770.48 h60
  text ".Layer_Name" at 427,-1008.49 h60
M11 Gerber Information:
  lines w10: -442,-1080.17 6158,-1080.17 ; -442,-876.83 6160,-876.83 ; -442,-673.5 -442,-1283.5 3563,-1283.5 6160,-1283.5 6160,-673.5 -441.5,-673.5 -441.5,-1283.5 1134,-1283.5 ; 2023,-1283.5 2023,-673.5 ; 3290,-876.83 3290,-673.5 ; 4130,-876.83 4130,-673.5 ; 4752,-1290 4752,-1087.17
  text "ALL ARTWORK VIEWED FROM TOP SIDE" at -378.5,-805.67 h60
  text "BOARD #:" at 2098,-805.67 h60
  text ".PRJ_Number" at 2643.5,-805.67 h60
  text "REV:" at 3488,-805.67 h60
  text ".PCB_Rev" at 3779.5,-805.67 h60
  text "SVN REV:" at 4326,-805.67 h60
  text ".VersionControl_RevNumber" at 4832,-805.67 h60
  text "LAYER NAME =" at -378.5,-1008.49 h60
  text "TID #:" at 2098,-1009 h60
  text ".TID" at 2643.5,-1009 h60
  text "PLOT NAME =" at -378.5,-1214.34 h60
  text ".plot_File_Name" at 427,-1214.34 h60
  text "GENERATED    :" at 2100,-1214.34 h60
  text ".Print_Date" at 2969.5,-1214.34 h60
  text ".Print_Time" at 3698.5,-1214.34 h60
  text "TEXAS INSTRUMENTS" at 4963,-1214.34 h60
M12 Stackup:
  drawing of 332 lines, arcs and shapes, not listed
  text "Layer" at 8208.5,4798.43 h60
  text "Name" at 8459.6,4798.43 h60
  text "Material" at 8945.17,4798.43 h60
  text "Thickness" at 9850,4798.43 h60
  text "Constant" at 10208.43,4798.43 h60
  text "Board Layer Stack" at 10540.16,4798.43 h60
  text "Top Overlay" at 8459.6,4678.43 h60
  text "Top Solder" at 8459.6,4558.43 h60
  text "Taiyo PSR 4000 HFX DI-GREEN" at 8945.17,4558.43 h60
  text "1.00mil" at 9850,4558.43 h60
  text "3.5" at 10208.43,4558.43 h60
  text "1" at 8208.5,4438.43 h60
  text "Top Layer" at 8459.6,4438.43 h60
  text "Copper Foil 18 microns" at 8945.17,4438.43 h60
  text "2.09mil" at 9849.94,4438.43 h60
  text "Dielectric 1" at 8459.6,4318.43 h60
  text "Iteq IT180A Prepreg 2113 RC58" at 8945.17,4318.43 h60
  text "3.51mil" at 9850,4318.43 h60
  text "4.13" at 10208.43,4318.43 h60
  text "2" at 8208.45,4198.43 h60
  text "GND 1" at 8459.6,4198.43 h60
  text "1.26mil" at 9850,4198.43 h60
  text "Dielectric 3" at 8459.6,4078.43 h60
  text "Iteq IT180A 4 mil core 1/1" at 8945.17,4078.43 h60
  text "4.00mil" at 9850,4078.43 h60
  text "4.4" at 10208.43,4078.43 h60
  text "3" at 8208.5,3958.43 h60
  text "SIG 1" at 8459.6,3958.43 h60
  text "1.26mil" at 9850,3958.43 h60
  text "Dielectric 5" at 8459.6,3838.43 h60
  text "Iteq IT180A Prepreg 106 RC71.5" at 8945.17,3838.43 h60
  text "1.75mil" at 9850,3838.43 h60
  text "3.79" at 10208.43,3838.43 h60
  text "Dielectric 7" at 8459.6,3718.43 h60
  text "Iteq IT180A Prepreg 1080 RC65" at 8945.17,3718.43 h60
  text "2.66mil" at 9849.94,3718.43 h60
  text "3.86" at 10208.43,3718.43 h60
  text "Dielectric1" at 8459.6,3598.43 h60
  text "Iteq IT180A 28 mil core H/H" at 8945.17,3598.43 h60
  text "28.00mil" at 9849.94,3598.43 h60
  text "4.53" at 10208.43,3598.43 h60
  text "Dielectric 8" at 8459.6,3478.43 h60
  text "Iteq IT180A Prepreg 1080 RC65" at 8945.17,3478.43 h60
  text "2.66mil" at 9849.94,3478.43 h60
  text "3.86" at 10208.43,3478.43 h60
  text "Dielectric 6" at 8459.6,3358.43 h60
  text "Iteq IT180A Prepreg 106 RC71.5" at 8945.17,3358.43 h60
  text "1.75mil" at 9850,3358.43 h60
  text "3.79" at 10208.43,3358.43 h60
  text "4" at 8208.5,3238.43 h60
  text "SIG 2" at 8459.6,3238.43 h60
  text "1.26mil" at 9850,3238.43 h60
  text "Dielectric 4" at 8459.6,3118.43 h60
  text "Iteq IT180A 4 mil core 1/1" at 8945.17,3118.43 h60
  text "4.00mil" at 9850,3118.43 h60
  text "4.4" at 10208.43,3118.43 h60
  text "5" at 8208.5,2998.43 h60
  text "GND 2" at 8459.6,2998.43 h60
  text "1.26mil" at 9850,2998.43 h60
  text "Dielectric 2" at 8459.6,2878.43 h60
  text "Iteq IT180A Prepreg 2113 RC58" at 8945.17,2878.43 h60
  text "3.51mil" at 9850,2878.43 h60
  text "4.13" at 10208.43,2878.43 h60
  text "6" at 8208.5,2758.43 h60
  text "Bottom Layer" at 8459.6,2758.43 h60
  text "Copper Foil 18 microns" at 8945.17,2758.43 h60
  text "2.09mil" at 9849.94,2758.43 h60
  text "Bottom Solder" at 8459.6,2638.43 h60
  text "Taiyo PSR 4000 HFX DI-GREEN" at 8945.17,2638.43 h60
  text "1.00mil" at 9850,2638.43 h60
  text "3.5" at 10208.43,2638.43 h60
  text "Bottom Overlay" at 8459.6,2518.43 h60
  text ".Layer_Name" at 427,-1008.49 h60
M13 Component Bodies Top:
  text ".Layer_Name" at 427,-1008.49 h60
M14 Component Bodies Bottom:
  text ".Layer_Name" at 427,-1008.49 h60
M15 Courtyards Top:
  text ".Layer_Name" at 427,-1008.49 h60
M16 Courtyards Bottom:
  text ".Layer_Name" at 427,-1008.49 h60
Drill Drawing:
  drawing of 183 lines, arcs and shapes, not listed
  text "Symbol" at -143.76,7572.18 h65.8
  text "Quantity" at 321.31,7572.18 h65.8
  text "Finished Hole Size" at 916.9,7572.18 h65.8
  text "Hole Length" at 2149.4,7572.18 h65.8
  text "Plated" at 3156.11,7572.18 h65.8
  text "Drill Layer Pair" at 3621.18,7572.18 h65.8
  text "Hole Tolerance (+)" at 4993.34,7572.18 h65.8
  text "Hole Tolerance (-)" at 6214.87,7572.18 h65.8
  text "104" at 321.31,7435.1 h54.83
  text "7.87mil (0.200mm)" at 916.9,7435.1 h54.83
  text "-" at 2149.4,7435.1 h54.83
  text "PTH" at 3156.11,7435.1 h54.83
  text "Top Layer - Bottom Layer" at 3621.18,7435.1 h54.83
  text "3.00mil (0.076mm)" at 4993.34,7435.1 h54.83
  text "3.00mil (0.076mm)" at 6214.87,7435.1 h54.83
  text "1523" at 321.31,7298.01 h54.83
  text "8.00mil (0.203mm)" at 916.9,7298.01 h54.83
  text "-" at 2149.4,7298.01 h54.83
  text "PTH" at 3156.11,7298.01 h54.83
  text "Top Layer - Bottom Layer" at 3621.18,7298.01 h54.83
  text "3.00mil (0.076mm)" at 4993.34,7298.01 h54.83
  text "3.00mil (0.076mm)" at 6214.87,7298.01 h54.83
  text "2" at 321.31,7160.93 h54.83
  text "23.62mil (0.600mm)" at 916.9,7160.93 h54.83
  text "51.18mil (1.300mm)" at 2149.4,7160.93 h54.83
  text "PTH" at 3156.11,7160.93 h54.83
  text "Top Layer - Bottom Layer" at 3621.18,7160.93 h54.83
  text "3.00mil (0.076mm)" at 4993.34,7160.93 h54.83
  text "3.00mil (0.076mm)" at 6214.87,7160.93 h54.83
  text "48" at 321.31,7023.84 h54.83
  text "32.00mil (0.813mm)" at 916.9,7023.84 h54.83
  text "-" at 2149.4,7023.84 h54.83
  text "NPTH" at 3156.11,7023.84 h54.83
  text "Top Layer - Bottom Layer" at 3621.18,7023.84 h54.83
  text "3.00mil (0.076mm)" at 4993.34,7023.84 h54.83
  text "3.00mil (0.076mm)" at 6214.87,7023.84 h54.83
  text "20" at 321.31,6886.76 h54.83
  text "35.43mil (0.900mm)" at 916.9,6886.76 h54.83
  text "-" at 2149.4,6886.76 h54.83
  text "PTH" at 3156.11,6886.76 h54.83
  text "Top Layer - Bottom Layer" at 3621.18,6886.76 h54.83
  text "3.00mil (0.076mm)" at 4993.34,6886.76 h54.83
  text "3.00mil (0.076mm)" at 6214.87,6886.76 h54.83
  text "10" at 321.31,6749.68 h54.83
  text "39.37mil (1.000mm)" at 916.9,6749.68 h54.83
  text "-" at 2149.4,6749.68 h54.83
  text "PTH" at 3156.11,6749.68 h54.83
  text "Top Layer - Bottom Layer" at 3621.18,6749.68 h54.83
  text "3.00mil (0.076mm)" at 4993.34,6749.68 h54.83
  text "3.00mil (0.076mm)" at 6214.87,6749.68 h54.83
  text "36" at 321.31,6612.59 h54.83
  text "40.00mil (1.016mm)" at 916.9,6612.59 h54.83
  text "-" at 2149.4,6612.59 h54.83
  text "PTH" at 3156.11,6612.59 h54.83
  text "Top Layer - Bottom Layer" at 3621.18,6612.59 h54.83
  text "3.00mil (0.076mm)" at 4993.34,6612.59 h54.83
  text "3.00mil (0.076mm)" at 6214.87,6612.59 h54.83
  text "88" at 321.31,6475.51 h54.83
  text "40.16mil (1.020mm)" at 916.9,6475.51 h54.83
  text "-" at 2149.4,6475.51 h54.83
  text "PTH" at 3156.11,6475.51 h54.83
  text "Top Layer - Bottom Layer" at 3621.18,6475.51 h54.83
  text "3.00mil (0.076mm)" at 4993.34,6475.51 h54.83
  text "3.00mil (0.076mm)" at 6214.87,6475.51 h54.83
  text "3" at 321.31,6338.42 h54.83
  text "47.24mil (1.200mm)" at 916.9,6338.42 h54.83
  text "-" at 2149.4,6338.42 h54.83
  text "PTH" at 3156.11,6338.42 h54.83
  text "Top Layer - Bottom Layer" at 3621.18,6338.42 h54.83
  text "3.00mil (0.076mm)" at 4993.34,6338.42 h54.83
  text "3.00mil (0.076mm)" at 6214.87,6338.42 h54.83
  text "2" at 321.31,6201.34 h54.83
  text "62.99mil (1.600mm)" at 916.9,6201.34 h54.83
  text "23.62mil (0.600mm)" at 2149.4,6201.34 h54.83
  text "PTH" at 3156.11,6201.34 h54.83
  text "Top Layer - Bottom Layer" at 3621.18,6201.34 h54.83
  text "3.00mil (0.076mm)" at 4993.34,6201.34 h54.83
  text "3.00mil (0.076mm)" at 6214.87,6201.34 h54.83
  text "4" at 321.31,6064.26 h54.83
  text "66.93mil (1.700mm)" at 916.9,6064.26 h54.83
  text "-" at 2149.4,6064.26 h54.83
  text "PTH" at 3156.11,6064.26 h54.83
  text "Top Layer - Bottom Layer" at 3621.18,6064.26 h54.83
  text "3.00mil (0.076mm)" at 4993.34,6064.26 h54.83
  text "3.00mil (0.076mm)" at 6214.87,6064.26 h54.83
  text "2" at 321.31,5927.17 h54.83
  text "82.68mil (2.100mm)" at 916.9,5927.17 h54.83
  text "23.62mil (0.600mm)" at 2149.4,5927.17 h54.83
  text "PTH" at 3156.11,5927.17 h54.83
  text "Top Layer - Bottom Layer" at 3621.18,5927.17 h54.83
  text "3.00mil (0.076mm)" at 4993.34,5927.17 h54.83
  text "3.00mil (0.076mm)" at 6214.87,5927.17 h54.83
  text "10" at 321.31,5790.09 h54.83
  text "126.00mil (3.200mm)" at 916.9,5790.09 h54.83
  text "-" at 2149.4,5790.09 h54.83
  text "NPTH" at 3156.11,5790.09 h54.83
  text "Top Layer - Bottom Layer" at 3621.18,5790.09 h54.83
  text "3.00mil (0.076mm)" at 4993.34,5790.09 h54.83
  text "3.00mil (0.076mm)" at 6214.87,5790.09 h54.83
  text "4" at 321.31,5653 h54.83
  text "127.95mil (3.250mm)" at 916.9,5653 h54.83
  text "-" at 2149.4,5653 h54.83
  text "NPTH" at 3156.11,5653 h54.83
  text "Top Layer - Bottom Layer" at 3621.18,5653 h54.83
  text "3.00mil (0.076mm)" at 4993.34,5653 h54.83
  text "3.00mil (0.076mm)" at 6214.87,5653 h54.83
  text "1856 Total" at 321.31,5515.92 h54.83
  text "Slot definitions :" at -143.76,5381.71 h54.83
  text "Routed Path Length" at 802.42,5381.71 h54.83
  text "= Calculated from tool start centre position to tool end centre position." at 1812.55,5381.71 h54.83
  text "Hole Length" at 802.42,5288.62 h54.83
  text "= Routed Path Length + Tool Size = Slot length as defined in the PCB layout" at 1437.98,5288.62 h54.83
  text ".Layer_Name" at 427,-1008.49 h60
M17 Embedded Cavity:
  text ".Layer_Name" at 427,-1008.49 h60
M18 Embedded Assembly:
  text ".Layer_Name" at 427,-1008.49 h60
M19 Embedded Keepout:
  text ".Layer_Name" at 427,-1008.49 h60
DXF_PROC109E2_TASY:
  drawing of 6230 lines, arcs and shapes, not listed
DXF_PROC109E2_BASY:
  drawing of 6782 lines, arcs and shapes, not listed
